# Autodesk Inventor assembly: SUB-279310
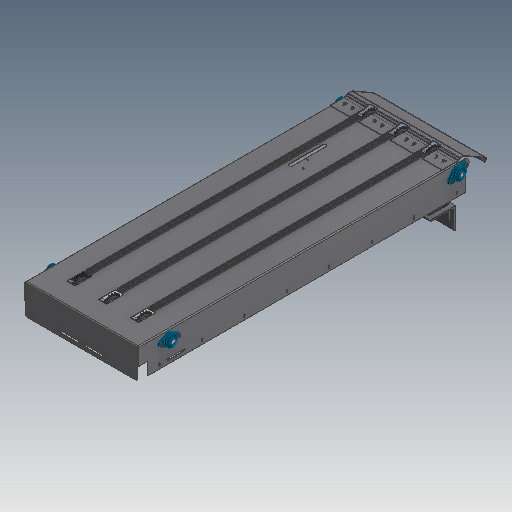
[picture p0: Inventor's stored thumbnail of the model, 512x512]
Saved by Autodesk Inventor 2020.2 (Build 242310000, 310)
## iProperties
Created: 2000-02
Part Number: SUB-279310
Document SubType Name: Assembly
Designer: sspink
Mass: 51270.8 g
Surface Area: 54030.8 cm^2
Volume: 12011.3 cm^3
Density: 4.26854 g/cm^3
Control State: 0
Master: False
Checked Out: False
Shininess: 0.0
Length Units: 11269
Angle Units: 11279
Time Units: 11290
Mass Units: 11283
Length Display Precision: 3
Angle Display Precision: 2
Compacted: True
Dimensions: 515,7x2089,1x746,5 mm
Mass: 51,271 kg
Density: 0.0
Volumn: 0.0
Area: 0.0
PropertySet Name: Model Information
Author: sspink
Revision Number: -
Title: SUB-279310
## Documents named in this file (24)
- D:\07 - DEMODATEN\OTX 2019 - Dataset - UPDATE - Dez2019\Designs\07-Packing machine\SUB-279310.iam
- D:\07 - DEMODATEN\OTX 2019 - Dataset - UPDATE - Dez2019\Designs\07-Packing machine\Parts\ADSK-011616.ipt
- D:\07 - DEMODATEN\OTX 2019 - Dataset - UPDATE - Dez2019\Designs\07-Packing machine\Parts\ADSK-011712.ipt
- D:\07 - DEMODATEN\OTX 2019 - Dataset - UPDATE - Dez2019\Designs\07-Packing machine\Parts\ADSK-011621.ipt
- D:\07 - DEMODATEN\OTX 2019 - Dataset - UPDATE - Dez2019\Designs\07-Packing machine\Parts\ADSK-011620.ipt
- D:\07 - DEMODATEN\OTX 2019 - Dataset - UPDATE - Dez2019\Designs\07-Packing machine\Parts\ADSK-011757.ipt
- D:\07 - DEMODATEN\OTX 2019 - Dataset - UPDATE - Dez2019\Designs\07-Packing machine\Parts\ADSK-011758.ipt
- D:\07 - DEMODATEN\OTX 2019 - Dataset - UPDATE - Dez2019\Designs\07-Packing machine\Parts\ADSK-011622.ipt
- D:\07 - DEMODATEN\OTX 2019 - Dataset - UPDATE - Dez2019\Designs\07-Packing machine\Parts\ADSK-011724.ipt
- D:\07 - DEMODATEN\OTX 2019 - Dataset - UPDATE - Dez2019\Designs\07-Packing machine\Parts\ADSK-011747.ipt
- D:\07 - DEMODATEN\OTX 2019 - Dataset - UPDATE - Dez2019\Designs\07-Packing machine\Parts\ADSK-011669.ipt
- D:\07 - DEMODATEN\OTX 2019 - Dataset - UPDATE - Dez2019\Designs\07-Packing machine\Parts\ADSK-011723.ipt
- D:\07 - DEMODATEN\OTX 2019 - Dataset - UPDATE - Dez2019\Designs\07-Packing machine\Parts\ADSK-011618.ipt
- D:\07 - DEMODATEN\OTX 2019 - Dataset - UPDATE - Dez2019\Content Center Files\de-DE\DIN 125-1  B\DIN 125-1 - B 6,4.ipt
- D:\07 - DEMODATEN\OTX 2019 - Dataset - UPDATE - Dez2019\Content Center Files\de-DE\ISO 4032(1)\ISO 4032 - M6DIN EN.ipt
- D:\07 - DEMODATEN\OTX 2019 - Dataset - UPDATE - Dez2019\Content Center Files\de-DE\ISO 10642(1)\ISO 10642 - M6x16.ipt
- D:\07 - DEMODATEN\OTX 2019 - Dataset - UPDATE - Dez2019\Content Center Files\de-DE\ISO 4762(2)\ISO 4762 - M6 x 16ISO.ipt
- D:\07 - DEMODATEN\OTX 2019 - Dataset - UPDATE - Dez2019\Content Center Files\de-DE\DIN 125-1  B\DIN 125-1 - B 8,4.ipt
- D:\07 - DEMODATEN\OTX 2019 - Dataset - UPDATE - Dez2019\Content Center Files\de-DE\ISO 4032(1)\ISO 4032 - M8DIN EN.ipt
- D:\07 - DEMODATEN\OTX 2019 - Dataset - UPDATE - Dez2019\Content Center Files\de-DE\ISO 4762(2)\ISO 4762 - M8 x 30ISO.ipt
- D:\07 - DEMODATEN\OTX 2019 - Dataset - UPDATE - Dez2019\Content Center Files\de-DE\ISO 2491 - A\ISO 2491 - A  6 x 4 x 32.ipt
- D:\07 - DEMODATEN\OTX 2019 - Dataset - UPDATE - Dez2019\Content Center Files\de-DE\ISO 2491 - A\ISO 2491 - A  5 x 3 x 32.ipt
- D:\07 - DEMODATEN\OTX 2019 - Dataset - UPDATE - Dez2019\Content Center Files\de-DE\ISO 4026\ISO 4026 - M5 x 10 - ISO.ipt
- D:\07 - DEMODATEN\OTX 2019 - Dataset - UPDATE - Dez2019\Content Center Files\de-DE\ISO 4762(2)\ISO 4762 - M6 x 35ISO.ipt
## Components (163 placed, 23 different names)
1. ADSK-011618:1 — Flush:8, Mate:10, Mate:11, Flush:14, Mate:15, Mate:16, Mate:17, Passend:18, Fluchtend:15, Fluchtend:16, Passend:20, Passend:22, Passend:24, Passend:26, Passend:28, Passend:30, Passend:32, Passend:34, Passend:53, Passend:54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
2. ADSK-011616:1 — Flush:1, Flush:2, Flush:6, Flush:7, Flush:8, Mate:11, Fluchtend:15
3. ADSK-011616:2 — Flush:1, Flush:7, Mate:17, Passend:18
4. ADSK-011616:3 — Flush:2, Flush:6, Mate:10, Fluchtend:16
5. ADSK-011622:1 — Passend:53, Passend:54, Passend:55
6. ADSK-011712:5 — Passend:115, Passend:116, Passend:117
7. ADSK-011712:6 — Passend:113, Passend:114
8. ADSK-011621:1 — Passend:109, Passend:110, Passend:116
9. ADSK-011758:1 — Fluchtend:20
10. ADSK-011758:2 — Passend:111
11. ADSK-011758:3 — Passend:112
12. ADSK-011747:1 — Passend:221, Passend:222
13. ADSK-011669:1 — Passend:184, Passend:220, Winkel:1
14. ADSK-011723:1 — Fluchtend:35
15. ADSK-011712:7 — Passend:213, Passend:216, Passend:219
16. ADSK-011712:8 — Passend:217, Passend:218
17. ADSK-011620:2 — Passend:212, Passend:213, Fluchtend:32, Passend:221, Passend:222
18. ADSK-011757:2 — Fluchtend:33
19. ADSK-011757:3 — Passend:214, Fluchtend:34
20. ADSK-011757:4 — Passend:215
21. ADSK-011724:1 — Fluchtend:34, Fluchtend:35
22. DIN 125-1 B B 8,4:9
23. DIN 125-1 B B 8,4:10
24. DIN 125-1 B B 8,4:11
25. DIN 125-1 B B 8,4:12
26. DIN 125-1 B B 8,4:13 — Einfügen:91
27. DIN 125-1 B B 8,4:14 — Einfügen:92
28. DIN 125-1 B B 8,4:15 — Einfügen:89
29. DIN 125-1 B B 8,4:16 — Einfügen:90
30. DIN EN 24032 M8:5
31. DIN EN 24032 M8:6
32. DIN EN 24032 M8:7
33. DIN EN 24032 M8:8
34. ISO 4762 M8 x 30:5
35. ISO 4762 M8 x 30:6
36. ISO 4762 M8 x 30:7
37. ISO 4762 M8 x 30:8
38. ISO 2491 A A  6 x 4 x 32:8
39. ISO 2491 A A  6 x 4 x 32:9
40. ISO 2491 A A  6 x 4 x 32:10
41. ISO 2491 A A  6 x 4 x 32:11
42. ISO 2491 A A  5 x 3 x 32:1
43. ISO 4026 M5 x 10:1
44. DIN 125-1 B B 6,4:35
45. DIN 125-1 B B 6,4:36
46. DIN 125-1 B B 6,4:37
47. DIN 125-1 B B 6,4:38
48. DIN 125-1 B B 6,4:39
49. DIN 125-1 B B 6,4:40
50. DIN 125-1 B B 6,4:41
51. DIN 125-1 B B 6,4:42
52. DIN EN 24032 M6:26
53. DIN EN 24032 M6:27
54. DIN EN 24032 M6:28
55. DIN EN 24032 M6:29
56. ISO 4762 M6 x 35:1
57. ISO 4762 M6 x 35:2
58. ISO 4762 M6 x 35:3
59. ISO 4762 M6 x 35:4
60. DIN 125-1 B B 6,4:27 — Passend:152, Passend:154, Passend:156, Passend:158, Passend:160, Passend:162, Passend:164, Passend:166
61. DIN 125-1 B B 6,4:28
62. DIN 125-1 B B 6,4:29
63. DIN 125-1 B B 6,4:30
64. DIN 125-1 B B 6,4:31
65. DIN 125-1 B B 6,4:32
66. DIN 125-1 B B 6,4:33
67. DIN 125-1 B B 6,4:34
68. ISO 4762 M6 x 16:1 — Passend:152
69. ISO 4762 M6 x 16:2 — Passend:154
70. ISO 4762 M6 x 16:3 — Passend:156
71. ISO 4762 M6 x 16:4 — Passend:158
72. ISO 4762 M6 x 16:5 — Passend:160
73. ISO 4762 M6 x 16:6 — Passend:162
74. ISO 4762 M6 x 16:7 — Passend:164
75. ISO 4762 M6 x 16:8 — Passend:166
76. DIN 125-1 B B 8,4:1
77. DIN 125-1 B B 8,4:2
78. DIN 125-1 B B 8,4:3
79. DIN 125-1 B B 8,4:4
80. DIN 125-1 B B 8,4:5 — Einfügen:48
81. DIN 125-1 B B 8,4:6 — Einfügen:47
82. DIN 125-1 B B 8,4:7 — Einfügen:46
83. DIN 125-1 B B 8,4:8 — Einfügen:45
84. DIN EN 24032 M8:1
85. DIN EN 24032 M8:2
86. DIN EN 24032 M8:3
87. DIN EN 24032 M8:4
88. ISO 4762 M8 x 30:1
89. ISO 4762 M8 x 30:2
90. ISO 4762 M8 x 30:3
91. ISO 4762 M8 x 30:4
92. ISO 2491 A A  6 x 4 x 32:1
93. ISO 2491 A A  6 x 4 x 32:2
94. ISO 2491 A A  6 x 4 x 32:3
95. DIN 125-1 B B 6,4:19 — Passend:57
96. DIN 125-1 B B 6,4:20 — Passend:59
97. DIN 125-1 B B 6,4:21 — Passend:61
98. DIN 125-1 B B 6,4:22 — Passend:63
99. DIN 125-1 B B 6,4:23 — Passend:65
100. DIN 125-1 B B 6,4:24 — Passend:67
101. DIN 125-1 B B 6,4:25 — Passend:69
102. DIN 125-1 B B 6,4:26 — Passend:71
103. DIN EN 24032 M6:18
104. DIN EN 24032 M6:19
105. DIN EN 24032 M6:20
106. DIN EN 24032 M6:21
107. DIN EN 24032 M6:22
108. DIN EN 24032 M6:23
109. DIN EN 24032 M6:24
110. DIN EN 24032 M6:25
111. DIN EN 24032 M6:1
112. DIN EN 24032 M6:2
113. DIN EN 24032 M6:3
114. DIN EN 24032 M6:4
115. DIN EN 24032 M6:5
116. DIN EN 24032 M6:6
117. DIN EN 24032 M6:7
118. DIN EN 24032 M6:8
119. DIN EN 24032 M6:9
120. DIN EN 24032 M6:10
121. DIN EN 24032 M6:11
122. DIN EN 24032 M6:12
123. DIN EN 24032 M6:13
124. DIN EN 24032 M6:14
125. DIN EN 24032 M6:15
126. DIN EN 24032 M6:16
127. DIN EN 24032 M6:17
128. ISO 10642 M6x16:1
129. ISO 10642 M6x16:2
130. ISO 10642 M6x16:3
131. ISO 10642 M6x16:4
132. ISO 10642 M6x16:5
133. ISO 10642 M6x16:6
134. ISO 10642 M6x16:7
135. ISO 10642 M6x16:8
136. ISO 10642 M6x16:9
137. ISO 10642 M6x16:10
138. ISO 10642 M6x16:11
139. ISO 10642 M6x16:12
140. ISO 10642 M6x16:13
141. ISO 10642 M6x16:14
142. ISO 10642 M6x16:15
143. ISO 10642 M6x16:16
144. ISO 10642 M6x16:17
145. ISO 10642 M6x16:18
146. DIN 125-1 B B 6,4:1 — Passend:20
147. DIN 125-1 B B 6,4:2 — Passend:22
148. DIN 125-1 B B 6,4:3 — Passend:24
149. DIN 125-1 B B 6,4:4 — Passend:26
150. DIN 125-1 B B 6,4:5 — Passend:28
151. DIN 125-1 B B 6,4:6 — Passend:30
152. DIN 125-1 B B 6,4:7 — Passend:32
153. DIN 125-1 B B 6,4:8
154. DIN 125-1 B B 6,4:9
155. DIN 125-1 B B 6,4:10
156. DIN 125-1 B B 6,4:11
157. DIN 125-1 B B 6,4:12
158. DIN 125-1 B B 6,4:13 — Passend:34
159. DIN 125-1 B B 6,4:14
160. DIN 125-1 B B 6,4:15
161. DIN 125-1 B B 6,4:16
162. DIN 125-1 B B 6,4:17
163. DIN 125-1 B B 6,4:18
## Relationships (76: Mate 54, Flush 13, Insert 8, Angle 1)
- Flush:1: ADSK-011616:1 ↔ ADSK-011616:2
- Flush:2: ADSK-011616:1 ↔ ADSK-011616:3
- Flush:6: ADSK-011616:1 ↔ ADSK-011616:3
- Flush:7: ADSK-011616:1 ↔ ADSK-011616:2
- Flush:8: ADSK-011618:1 ↔ ADSK-011616:1
- Mate:10: ADSK-011618:1 ↔ ADSK-011616:3
- Mate:11: ADSK-011618:1 ↔ ADSK-011616:1
- Flush:14: ADSK-011618:1
- Mate:15: ADSK-011618:1
- Mate:16: ADSK-011618:1
- Mate:17: ADSK-011618:1 ↔ ADSK-011616:2
- Passend:18 [Mate]: ADSK-011618:1 ↔ ADSK-011616:2
- Fluchtend:15 [Flush]: ADSK-011618:1 ↔ ADSK-011616:1
- Fluchtend:16 [Flush]: ADSK-011618:1 ↔ ADSK-011616:3
- Passend:20 [Mate]: ADSK-011618:1 ↔ DIN 125-1 B B 6,4:1
- Passend:22 [Mate]: ADSK-011618:1 ↔ DIN 125-1 B B 6,4:2
- Passend:24 [Mate]: ADSK-011618:1 ↔ DIN 125-1 B B 6,4:3
- Passend:26 [Mate]: ADSK-011618:1 ↔ DIN 125-1 B B 6,4:4
- Passend:28 [Mate]: ADSK-011618:1 ↔ DIN 125-1 B B 6,4:5
- Passend:30 [Mate]: ADSK-011618:1 ↔ DIN 125-1 B B 6,4:6
- Passend:32 [Mate]: ADSK-011618:1 ↔ DIN 125-1 B B 6,4:7
- Passend:34 [Mate]: ADSK-011618:1 ↔ DIN 125-1 B B 6,4:13
- Passend:53 [Mate]: ADSK-011618:1 ↔ ADSK-011622:1
- Passend:54 [Mate]: ADSK-011618:1 ↔ ADSK-011622:1
- Passend:55 [Mate]: ADSK-011618:1 ↔ ADSK-011622:1
- Passend:57 [Mate]: ADSK-011618:1 ↔ DIN 125-1 B B 6,4:19
- Passend:59 [Mate]: ADSK-011618:1 ↔ DIN 125-1 B B 6,4:20
- Passend:61 [Mate]: ADSK-011618:1 ↔ DIN 125-1 B B 6,4:21
- Passend:63 [Mate]: ADSK-011618:1 ↔ DIN 125-1 B B 6,4:22
- Passend:65 [Mate]: ADSK-011618:1 ↔ DIN 125-1 B B 6,4:23
- Passend:67 [Mate]: ADSK-011618:1 ↔ DIN 125-1 B B 6,4:24
- Passend:69 [Mate]: ADSK-011618:1 ↔ DIN 125-1 B B 6,4:25
- Passend:71 [Mate]: ADSK-011618:1 ↔ DIN 125-1 B B 6,4:26
- Passend:109 [Mate]: ADSK-011618:1 ↔ ADSK-011621:1
- Passend:110 [Mate]: ADSK-011618:1 ↔ ADSK-011621:1
- Passend:111 [Mate]: ADSK-011618:1 ↔ ADSK-011758:2
- Passend:112 [Mate]: ADSK-011618:1 ↔ ADSK-011758:3
- Fluchtend:20 [Flush]: ADSK-011618:1 ↔ ADSK-011758:1
- Passend:113 [Mate]: ADSK-011618:1 ↔ ADSK-011712:6
- Passend:114 [Mate]: ADSK-011618:1 ↔ ADSK-011712:6
- Passend:115 [Mate]: ADSK-011618:1 ↔ ADSK-011712:5
- Passend:116 [Mate]: ADSK-011712:5 ↔ ADSK-011621:1
- Passend:117 [Mate]: ADSK-011618:1 ↔ ADSK-011712:5
- Einfügen:45 [Insert]: ADSK-011618:1 ↔ DIN 125-1 B B 8,4:8
- Einfügen:46 [Insert]: ADSK-011618:1 ↔ DIN 125-1 B B 8,4:7
- Einfügen:47 [Insert]: ADSK-011618:1 ↔ DIN 125-1 B B 8,4:6
- Einfügen:48 [Insert]: ADSK-011618:1 ↔ DIN 125-1 B B 8,4:5
- Passend:152 [Mate]: DIN 125-1 B B 6,4:27 ↔ ISO 4762 M6 x 16:1
- Passend:154 [Mate]: DIN 125-1 B B 6,4:27 ↔ ISO 4762 M6 x 16:2
- Passend:156 [Mate]: DIN 125-1 B B 6,4:27 ↔ ISO 4762 M6 x 16:3
- Passend:158 [Mate]: DIN 125-1 B B 6,4:27 ↔ ISO 4762 M6 x 16:4
- Passend:160 [Mate]: DIN 125-1 B B 6,4:27 ↔ ISO 4762 M6 x 16:5
- Passend:162 [Mate]: DIN 125-1 B B 6,4:27 ↔ ISO 4762 M6 x 16:6
- Passend:164 [Mate]: DIN 125-1 B B 6,4:27 ↔ ISO 4762 M6 x 16:7
- Passend:166 [Mate]: DIN 125-1 B B 6,4:27 ↔ ISO 4762 M6 x 16:8
- Passend:184 [Mate]: ADSK-011618:1 ↔ ADSK-011669:1
- Passend:212 [Mate]: ADSK-011618:1 ↔ ADSK-011620:2
- Passend:213 [Mate]: ADSK-011712:7 ↔ ADSK-011620:2
- Fluchtend:32 [Flush]: ADSK-011618:1 ↔ ADSK-011620:2
- Fluchtend:33 [Flush]: ADSK-011618:1 ↔ ADSK-011757:2
- Passend:214 [Mate]: ADSK-011618:1 ↔ ADSK-011757:3
- Passend:215 [Mate]: ADSK-011618:1 ↔ ADSK-011757:4
- Passend:216 [Mate]: ADSK-011618:1 ↔ ADSK-011712:7
- Einfügen:89 [Insert]: ADSK-011618:1 ↔ DIN 125-1 B B 8,4:15
- Einfügen:90 [Insert]: ADSK-011618:1 ↔ DIN 125-1 B B 8,4:16
- Einfügen:91 [Insert]: ADSK-011618:1 ↔ DIN 125-1 B B 8,4:13
- Einfügen:92 [Insert]: ADSK-011618:1 ↔ DIN 125-1 B B 8,4:14
- Passend:217 [Mate]: ADSK-011618:1 ↔ ADSK-011712:8
- Passend:218 [Mate]: ADSK-011618:1 ↔ ADSK-011712:8
- Passend:219 [Mate]: ADSK-011618:1 ↔ ADSK-011712:7
- Fluchtend:34 [Flush]: ADSK-011757:3 ↔ ADSK-011724:1
- Fluchtend:35 [Flush]: ADSK-011723:1 ↔ ADSK-011724:1
- Passend:220 [Mate]: ADSK-011618:1 ↔ ADSK-011669:1
- Passend:221 [Mate]: ADSK-011747:1 ↔ ADSK-011620:2
- Passend:222 [Mate]: ADSK-011747:1 ↔ ADSK-011620:2
- Winkel:1 [Angle]: ADSK-011618:1 ↔ ADSK-011669:1
## Named parameters: d278_d284 = 0, d407_d392 = 0, d408_d393 = 0, d409_d394 = 0, d410_d395 = 0, d411_d396 = 0, d412_d397 = 0, d413_d398 = 0, d414_d399 = 0, d415_d400 = 0, d416_d401 = 0, d417_d402 = 0, d418_d370 = 0, d419_d372 = 0, d420_d373 = 0, d421_d374 = 0, d422_d375 = 0, d423_d376 = 0, d424_d377 = 0, d425_d382 = 0, d426_d383 = 0, d427_d384 = 0, d428_d385 = 0, d429_d386 = 0, d430_d387 = 0, d431_d388 = 0, d432_d389 = 0, d433_d390 = 0, d434_d391 = 0, d443_d379 = 0, d444_d380 = 0, d445_d381 = 0, d462_d302 = 0, d463_d303 = 0, d474_d286 = 0, d475_d287 = 0, d476_d290 = 0, d477_d291 = 0
